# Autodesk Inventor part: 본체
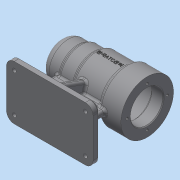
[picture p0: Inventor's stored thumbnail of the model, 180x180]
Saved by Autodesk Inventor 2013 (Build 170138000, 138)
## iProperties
Created: 2016-06
Part Number: 본체
Material: 일반
Document SubType Name: Modeling
Designer: dgall
Density: 1 g/cm^3
Author: dgall
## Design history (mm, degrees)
sketch "스케치1"
  geometry: L1 (-56, 0)-(56, 0); L2 (-56, 0)-(-56, 25); L3 (-56, 25)-(-31, 25); L4 (-31, 25)-(-31, 27); L5 (-31, 27)-(-11, 27); L6 (-11, 27)-(-11, 30); L7 (-11, 30)-(28, 30); L8 (28, 34)-(56, 34); L9 (56, 34)-(56, 21); L10 (-50, 0)-(-50, 10.5); L11 (-50, 10.5)-(-47, 10.5); L12 (-47, 10.5)-(-47, 16); L13 (-47, 16)-(-43, 16); L14 (-43, 16)-(-43, 17.5); L15 (-43, 17.5)-(-25, 17.5); L16 (-25, 17.5)-(-25, 21); L17 (-25, 21)-(-13, 21); L18 (-13, 21)-(-13, 24); L19 (-13, 24)-(41, 24); L20 (41, 24)-(41, 21); L21 (41, 21)-(56, 21); L22 (-56, 0)-(-50, 0); L23 (28, 34)-(28, 30); 2 further points
  constraints: 46 end point, 16 parallel, 4 perpendicular, 1 coincident, 1 collinear, 1 horizontal, 1 midpoint, 1 point on line, 1 vertical, 1 vertical alignment
  dimensions: "d0" = 112 distance of L1.start L1.end; "d3" = 21 diameter of L11 L1; "d4" = 32 diameter of L13 L1; "d5" = 35 diameter of L15 L1; "d6" = 42 diameter of L17 L1; "d7" = 48 diameter of L19 L1; "d8" = 42 diameter of L21 L1; "d9" = 50 diameter of L3 L1; "d10" = 54 diameter of L5 L1; "d11" = 60 diameter of L7 L1; "d12" = 68 diameter of L8 L1; "d13" = 3 distance of L10.end L11.end; "d14" = 4 distance of L12.end L13.end; "d15" = 18 distance of L14.end L15.end; "d16" = 12 distance of L16.end L17.end; "d17" = 54 distance of L18.end L19.end; "d18" = 15 distance of L9.end L20.end; "d19" = 25 distance between parallel lines of L4 L2; "d20" = 45 distance between parallel lines of L6 L2; "d22" = 84 distance between parallel lines of L23 L2
revolve "회전1" sketch "스케치1" stored, may be unused: angle "d23" = 90 deg
fillet "모깎기1" dims "d24" = 10
fillet "모깎기2" dims "d25" = 3
fillet "모깎기3" dims "d26" = 0.3
chamfer "모따기1" distance "d27" = 1; stored, may be unused: second distance "d28" = 2, angle "d29" = 45 deg
sketch "스케치2" dims "d30" = 52
  geometry: C1 r 34 at (0, 0) reference; C2 r 22 at (0, 0) reference; 2 further points
  constraints: 2 vertical alignment, 1 coincident, 2 other
hole "구멍1" sketch "스케치2" at (0, 26) diameter "d31" = 3.242; stored, may be unused: countersink angle "d35" = 90 deg, drill point angle "d37" = 118 deg; dims "d32" = 8, "d33" = 4, "d34" = 2, "d36" = 11
fillet "모깎기4" dims "d41" = 3
node "작업 평면1"
sketch "스케치3"
  geometry: L1 (46, -35)-(-46, -35); L2 (-56, -25)-(-56, 25); L3 (-46, 35)-(46, 35); L4 (56, 25)-(56, -25); L5 (-36, 4)-(36, 4); L6 (36, 4)-(36, -4); L7 (36, -4)-(-36, -4); L8 (-36, -4)-(-36, 4); A1 r 10 centre (46, -25) between (46, -35) and (56, -25); A2 r 10 centre (-46, 25) between (-46, 35) and (-56, 25); A3 r 10 centre (-46, -25) between (-56, -25) and (-46, -35); A4 r 10 centre (46, 25) between (56, 25) and (46, 35); 8 further points
  constraints: 16 end point, 8 point on circle, 8 tangent, 6 point on line, 4 centre point, 4 midpoint, 4 parallel, 3 equal radius, 2 horizontal, 2 horizontal alignment, 2 perpendicular, 2 vertical alignment
  dimensions: "d43" = 112 distance of point (56, -35) point (-56, -35); "d45" = 70 distance of point (-56, -35) point (-56, 35); "d46" = 10 radius of A1; "d47" = 8 distance of L7.end L5.start; "d48" = 20 distance between parallel lines of L6 L4
extrude "돌출1" join sketch "스케치3" distance "d49" = 10; taper "d50" = 0 deg
extrude "돌출2" join sketch "스케치3" stored distance "d51" = 10; taper "d52" = 0 deg
chamfer "모따기2" distance "d53" = 4; stored, may be unused: second distance "d54" = 2, angle "d55" = 45 deg
hole "구멍2" diameter "d58" = 5; stored, may be unused: countersink angle "d62" = 90 deg, drill point angle "d64" = 118 deg; dims "d56" = 10, "d57" = 10, "d59" = 8, "d60" = 9, "d61" = 4, "d63" = 11
sketch "스케치6"
  geometry: L1 (-60, 25)-(-60, -25) reference; L2 (-60, 29.5)-(-60, 20.5) reference; L3 (-60, 28)-(-27.62, 16.214); L4 (-70, 35)-(-64, 35) reference; A1 r 30 centre (0, 0) between (-29.732, -4) and (-29.732, 4) reference; 1 further point
  constraints: 2 end point, 1 point on line
  dimensions: "d65" = 7 distance from line of L3.start L4; "d66" = 110 deg angle of L2 L3
feature "리브1" sketch "스케치6" dims "d67" = 1, "d68" = 8, "d69" = 0, "d70" = 0, "d71" = 1, "d72" = 1
fillet "모깎기5" dims "d73" = 3
fillet "모깎기6" dims "d74" = 3
node "작업 평면3"
sketch "스케치7"
  geometry: L1 (-20.5, 10)-(19.5, 10); L2 (19.5, 10)-(19.5, -10); L3 (19.5, -10)-(-20.5, -10); L4 (-20.5, -10)-(-20.5, 10); L5 (47.5, -34)-(47.5, 34) reference; 5 further points
  constraints: 4 midpoint, 2 horizontal alignment, 1 vertical alignment, 2 other
  dimensions: "d76" = 40 distance of L1.start L1.end; "d78" = 20 distance of L1.end L2.end; "d79" = 48 distance from line of point (-0.5, 10) L5
feature "엠보싱1" sketch "스케치7" dims "d0" = 112, "d3" = 21, "d4" = 32, "d5" = 35, "d6" = 42, "d7" = 48, "d8" = 42, "d9" = 50, "d10" = 54, "d11" = 60, "d12" = 68, "d13" = 3, "d14" = 4, "d15" = 18, "d16" = 12, "d17" = 54, "d18" = 15, "d19" = 25, "d20" = 45, "d22" = 84, "d80" = 0.5, "d81" = 0
node "솔리드1"
pattern_circular "원형 패턴1" dims angle "d39" = 360 deg
mirror "대칭1"
mirror "대칭3"
mirror "대칭4"
